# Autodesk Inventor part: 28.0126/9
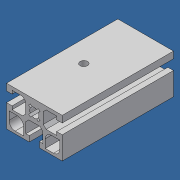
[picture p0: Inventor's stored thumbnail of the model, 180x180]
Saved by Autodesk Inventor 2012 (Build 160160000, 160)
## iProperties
Created: 2007-06
Part Number: 28.0126/9
Material: Aluminum-6061
Document SubType Name: Modeling
Designer: Andy Moles
Density: 2.71 g/cm^3
Description: L = 3.543" MILL TO 28.0126/9
Stock Number: 20.1055 45X32F
Vendor: F
Mass: 143.334 g
Surface Area: 366.702 cm^2
Volume: 52.891 cm^3
Author: Andy Moles
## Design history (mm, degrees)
sketch "Sketch1"
  geometry: L1 (-4.596, -3.182)-(-3.263, -1.849) reference; L2 (-3.263, 1.849)-(-4.596, 3.182) reference; L3 (-4.596, 3.182)-(-3.182, 4.596) reference; L4 (-3.182, 4.596)-(-1.849, 3.263) reference; L5 (1.849, 3.263)-(3.182, 4.596) reference; L6 (3.182, 4.596)-(4.596, 3.182) reference; L7 (4.596, 3.182)-(3.263, 1.849) reference; L8 (3.263, -1.849)-(4.596, -3.182) reference; L9 (4.596, -3.182)-(3.182, -4.596) reference; L10 (3.182, -4.596)-(1.849, -3.263) reference; L11 (-1.849, -3.263)-(-3.182, -4.596) reference; L12 (-3.182, -4.596)-(-4.596, -3.182) reference; L13 (13.8, -8.8)-(20.5, -8.8) reference; L14 (20.5, -8.8)-(20.5, -15.5) reference; L15 (15.5, -20.5)-(8.8, -20.5) reference; L16 (8.8, -20.5)-(8.8, -13.8) reference; L17 (-20.5, -8.8)-(-13.8, -8.8) reference; L18 (-8.8, -13.8)-(-8.8, -20.5) reference; L19 (-8.8, -20.5)-(-15.5, -20.5) reference; L20 (-4.1, -22.5)-(-4.1, -18) reference; L21 (-4.6, -18)-(-6.8, -18) reference; L22 (-6.8, -18)-(-6.8, -9.5) reference; L23 (-6.8, -9.5)-(-4.5, -7.2) reference; L24 (-4.5, -7.2)-(4.5, -7.2) reference; L25 (4.5, -7.2)-(6.8, -9.5) reference; L26 (6.8, -9.5)-(6.8, -18) reference; L27 (4.1, -18)-(4.1, -22.5) reference; L28 (22.5, -22.5)-(4.4, -22.5) reference; L29 (22.5, -4.1)-(18, -4.1) reference; L30 (18, -4.1)-(18, -6.8); L31 (18, -6.8)-(9.5, -6.8) reference; L32 (9.5, -6.8)-(7.2, -4.5) reference; L33 (7.2, -4.5)-(7.2, 4.5) reference; L34 (7.2, 4.5)-(9.5, 6.8) reference; L35 (9.5, 6.8)-(18, 6.8) reference; L36 (18, 4.1)-(22.5, 4.1) reference; L37 (-22.5, 9.5)-(22.5, 9.5) reference; L38 (-22.5, 4.1)-(-18, 4.1) reference; L39 (-18, 4.1)-(-18, 6.8); L40 (-18, 6.8)-(-9.5, 6.8) reference; L41 (-9.5, 6.8)-(-7.2, 4.5) reference; L42 (-7.2, 4.5)-(-7.2, -4.5) reference; L43 (-7.2, -4.5)-(-9.5, -6.8) reference; L44 (-9.5, -6.8)-(-18, -6.8) reference; L45 (-18, -4.1)-(-22.5, -4.1) reference; L46 (-22.5, -22.5)-(-22.5, -4.4) reference; L47 (-22.5, -4.4)-(-22.5, -4.1) reference; L48 (-22.5, 4.1)-(-22.5, 9.5) reference; L49 (22.5, 9.5)-(22.5, 4.1) reference; L50 (4.4, -22.5)-(4.1, -22.5) reference; L51 (-4.1, -22.5)-(-22.5, -22.5) reference; L52 (-18, -6.8)-(-18, -4.1) reference; L53 (-20.5, -15.5)-(-20.5, -8.8) reference; L54 (6.8, -18)-(4.1, -18) reference; L55 (-4.1, -18)-(-4.6, -18) reference; L56 (18, 6.8)-(18, 4.1) reference; L57 (22.5, -4.1)-(22.5, -22.5); A1 r 5 centre (13.8, -13.8) between (13.8, -8.8) and (8.8, -13.8) reference; A2 r 5 centre (15.5, -15.5) between (15.5, -20.5) and (20.5, -15.5) reference; A3 r 5 centre (-13.8, -13.8) between (-8.8, -13.8) and (-13.8, -8.8) reference; A4 r 5 centre (-15.5, -15.5) between (-20.5, -15.5) and (-15.5, -20.5) reference; A5 r 3.75 centre (0, 0) between (-3.362, 1.66) and (-3.263, -1.849) reference; A6 r 3.75 centre (0, 0) between (-1.849, -3.263) and (-1.66, -3.362) reference; A7 r 3.75 centre (0, 0) between (1.66, 3.362) and (-1.849, 3.263) reference; A8 r 3.75 centre (0, 0) between (-3.263, 1.849) and (-3.362, 1.66) reference; A9 r 3.75 centre (0, 0) between (3.362, -1.66) and (3.263, 1.849) reference; A10 r 3.75 centre (0, 0) between (1.849, 3.263) and (1.66, 3.362) reference; A11 r 3.75 centre (0, 0) between (-1.66, -3.362) and (1.849, -3.263) reference; A12 r 3.75 centre (0, 0) between (3.263, -1.849) and (3.362, -1.66) reference
  constraints: 114 end point, 24 point on circle, 20 horizontal, 15 vertical, 12 centre point, 1 parallel, 108 other
extrude "Extrusion1" new body sketch "Sketch1" stored distance "d0" = 89.9922; taper "d1" = 0 deg
sketch "Sketch2"
  geometry: L1 (0, 89.992)-(0, 0) reference; C1 r 3 at (17.5, 44.996); 1 further point
  constraints: 1 centre point, 1 horizontal alignment
  dimensions: "d4" = 6 diameter of C1; "d5" = 17.5 distance from line of C1.centre L1
extrude "Extrusion2" cut sketch "Sketch2" stored distance "d2" = 10; taper "d3" = 0 deg
body "Solid1"
